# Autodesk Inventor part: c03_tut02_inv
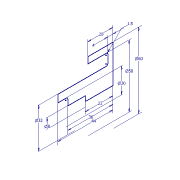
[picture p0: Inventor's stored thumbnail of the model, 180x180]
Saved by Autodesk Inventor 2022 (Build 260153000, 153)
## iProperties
Created: 2017-04
Part Number: c03_tut02_inv
Material: Generic
Document SubType Name: Modeling
Designer: CADCIM 00
Density: 1 g/cm^3
Appearance: Default
Author: CADCIM 00
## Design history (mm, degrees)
sketch "Sketch1"
  geometry: L1 (0, 0)-(-22, 0); L2 (-22, 0)-(-22, 4); L3 (-22, 4)-(-36, 4); L4 (-36, 4)-(-36, 8.5); L5 (-37.5, 10)-(-44, 10); L6 (-44, 10)-(-44, 16); L7 (-44, 16)-(-5.5, 16); L8 (-4, 17.5)-(-4, 23.5); L9 (-5.5, 25)-(-20, 25); L10 (-20, 25)-(-20, 30); L11 (-20, 30)-(0, 30); L12 (0, 30)-(0, 0); A1 r 1.5 centre (-5.5, 23.5) between (-4, 23.5) and (-5.5, 25); A2 r 1.5 centre (-37.5, 8.5) between (-36, 8.5) and (-37.5, 10); A3 r 1.5 centre (-5.5, 17.5) between (-5.5, 16) and (-4, 17.5)
  constraints: 24 end point, 11 perpendicular, 6 point on circle, 6 tangent, 3 centre point, 2 equal radius, 1 horizontal
  dimensions: "d0" = 8 diameter of L3 L1; "d1" = 20 diameter of L5 L1; "d2" = 32 diameter of L7 L1; "d3" = 50 diameter of L9 L1; "d4" = 60 diameter of L11 L1; "d5" = 4 distance between parallel lines of L8 L12; "d6" = 20 distance of L10.end L11.end; "d7" = 22 distance of L1.start L1.end; "d9" = 36 distance between parallel lines of L4 L12; "d10" = 44 distance between parallel lines of L12 L6; "d11" = 1.5 radius of A1
